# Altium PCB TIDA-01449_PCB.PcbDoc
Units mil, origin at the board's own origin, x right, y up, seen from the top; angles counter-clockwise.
Board outline 718.74 x 413.39 mil, 2 copper layers (Top Layer, Bottom Layer), stack 62 mil thick; 17 components, 10 nets, 40 pads, 19 vias.
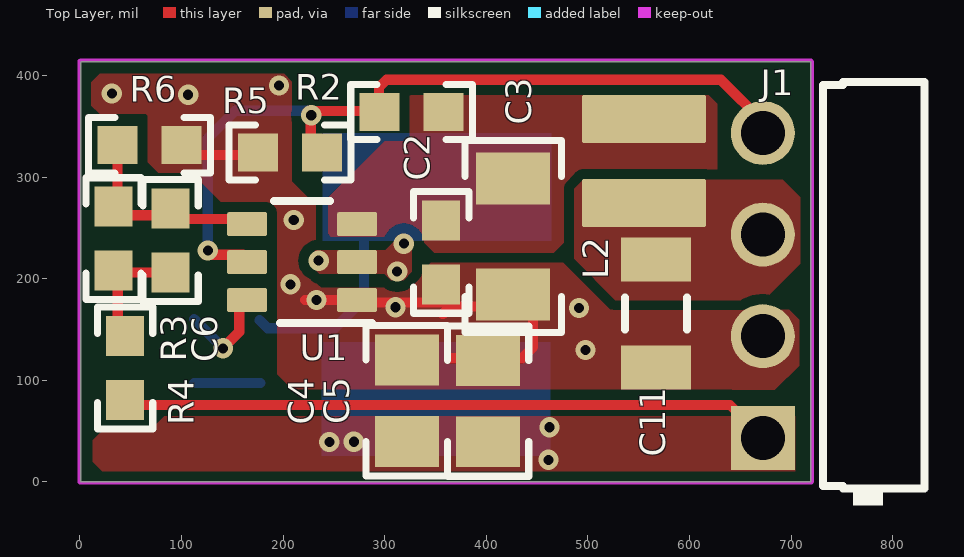
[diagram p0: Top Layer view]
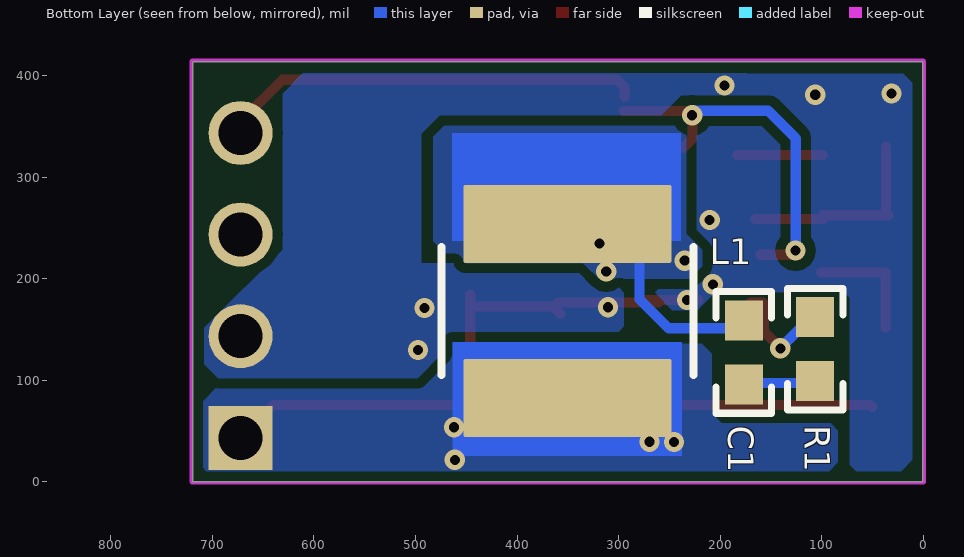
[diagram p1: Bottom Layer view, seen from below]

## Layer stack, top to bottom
Top Solder: solder mask 0.4, Solder Resist, Dk 3.5
Top Layer: signal copper 1.4
Dielectric1: core 59.2, FR-4, Dk 4.8
Bottom Layer: signal copper 1.4
Bottom Solder: solder mask 0.4, Solder Resist, Dk 3.5

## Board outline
0.56,0.27 0.56,413.66 719.3,413.66 719.3,0.27

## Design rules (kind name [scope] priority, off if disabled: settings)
AcuteAngle [All] p1: minimum=4.50000000000000E+0001 checktracksonly=FALSE
AssemblyTestPointUsage [All] p1: valid=2
BoardOutlineClearance BoardOutlineClearance_MountingHoles [OnCopper and InComponentClass('Mounting Holes')] p1: gap=40 ignorepadtopadclearanceinfootprint=FALSE
BoardOutlineClearance BoardOutlineClearance_Poly [OnCopper and IsPoly] p2: gap=10 ignorepadtopadclearanceinfootprint=FALSE
BoardOutlineClearance [OnCopper and Not InComponentClass('Logo') and not InComponentClass('FiducialMark') and not InRegion(1000,500,4000,800) and not InPoly] p3: gap=10 ignorepadtopadclearanceinfootprint=FALSE
Clearance Clearance_Keepouts [((IsTrack Or IsArc) And Not InPoly) And IsFree and IsKeepOut vs ((IsTrack Or IsArc) And Not InPoly) And IsFree and IsKeepOut] p1: gap=0 ignorepadtopadclearanceinfootprint=FALSE
Clearance Clearance_Poly [InPolygon] p2: gap=10 ignorepadtopadclearanceinfootprint=FALSE except(0: Arc-Hole Track-Hole SMDPad-Hole THPad-Hole Via-Hole Fill-Hole Poly-Hole Region-Hole Text-Hole)
Clearance [All] p3: gap=7.87 ignorepadtopadclearanceinfootprint=FALSE except(0: Arc-Hole Track-Hole SMDPad-Hole THPad-Hole Via-Hole Fill-Hole Poly-Hole Region-Hole Text-Hole)
ComponentClearance ComponentClearance_MountingHoles_FiducialMarks [InComponentClass('Mounting Holes') vs InComponentClass('FiducialMark')] p1: gap=50 collisioncheckmode=3 verticalgap=10 showdistances=FALSE
ComponentClearance ComponentClearance_Shunt [InComponentClass('Header') vs InComponentClass('Shunt')] p2: gap=0 collisioncheckmode=3 verticalgap=0 showdistances=FALSE
ComponentClearance ComponentClearance_Logo [InComponentClass('Logo')] p3: gap=50 collisioncheckmode=3 verticalgap=10 showdistances=FALSE
ComponentClearance ComponentClearance_ScrewToNut [(HasFootprint('NY PMS 440 0025 PH')) vs (HasFootprint('Keystone_1902C'))] p4: gap=5 collisioncheckmode=3 verticalgap=10 showdistances=FALSE
ComponentClearance ComponentClearance_MountingHoles [InComponentClass('Mounting Holes')] p5: gap=250 collisioncheckmode=3 verticalgap=100000 showdistances=FALSE
ComponentClearance ComponentClearance_SmallPassives [HasFootprint('0201*') or HasFootprint('0402*') or HasFootprint('0508') or HasFootprint('0603*') or HasFootprint('0612') or HasFootprint('0805*') or HasFootprint('0815*') or HasFootprint('0830*') or HasFootprint('1206*') or HasFootprint('1210*') or HasFootprint('1808*') or HasFootprint('1812*') or HasFootprint('1825*') or HasFootprint('2010*') or HasFootprint('2220*') or HasFootprint('2225*') or HasFootprint('2512*') or HasFootprint('2728*') or HasFootprint('3518*') vs HasFootprint('0201*') or HasFootprint('0402*') or HasFootprint('0508') or HasFootprint('0603*') or HasFootprint('0612') or HasFootprint('0805*') or HasFootprint('0815*') or HasFootprint('0830*') or HasFootprint('1206*') or HasFootprint('1210*') or HasFootprint('1808*') or HasFootprint('1812*') or HasFootprint('1825*') or HasFootprint('2010*') or HasFootprint('2220*') or HasFootprint('2225*') or HasFootprint('2512*') or HasFootprint('2728*') or HasFootprint('3518*')] p6: gap=14.96 collisioncheckmode=3 verticalgap=10 showdistances=FALSE
ComponentClearance ComponentClearance_THtoSMT [IsThruComponent vs IsSMTComponent] p7: gap=40 collisioncheckmode=3 verticalgap=30 showdistances=FALSE
ComponentClearance ComponentClearance_THtoSMT_1 [(ObjectKind = 'Component') And (Name = 'L2') vs (ObjectKind = 'Component') And (Name = 'C11')] p8: gap=18 collisioncheckmode=3 verticalgap=30 showdistances=FALSE
ComponentClearance ComponentClearance_THtoTH [IsThruComponent vs IsThruComponent] p9: gap=30 collisioncheckmode=3 verticalgap=30 showdistances=FALSE
ComponentClearance [All] p10: gap=30 collisioncheckmode=3 verticalgap=10 showdistances=FALSE
DiffPairsRouting [All] p1: maxlimit=100 minlimit=10 mostfreqgap=10 toplayer_minwidth=15 toplayer_maxwidth=15 toplayer_prefwidth=15 bottomlayer_minwidth=15 bottomlayer_maxwidth=15 bottomlayer_prefwidth=15 maxuncoupledlength=1000
FabricationTestPointUsage TestPointUsage [All] p1: valid=2 allowmultiple=FALSE
FabricationTestpoint Testpoint [All] p1: side=3 testpointundercomponent=TRUE minsize=40 maxsize=100 preferedsize=60 minholesize=0 maxholesize=40 preferedholesize=32 testpointgrid=1 allowsidetop=TRUE allowsidebottom=TRUE usegrid=TRUE gridtolerance=0.01
FanoutControl Fanout_LCC [IsLCC] p1: bgadir=Out bgaviamode=Centered fanoutstyle=Auto fanoutdirection=Alternating viagrid=1 // Fanout_LCC (Default Rule)
FanoutControl Fanout_BGA [IsBGA] p2: bgadir=Out bgaviamode=Centered fanoutstyle=Auto fanoutdirection=Alternating viagrid=1 // Fanout_BGA (Default Rule)
FanoutControl Fanout_Default [All] p4: bgadir=Out bgaviamode=Centered fanoutstyle=Auto fanoutdirection=Alternating viagrid=1 // Fanout_Default (Default Rule)
FanoutControl Fanout_Small [(CompPinCount < 5)] p5: bgadir=Out bgaviamode=Centered fanoutstyle=Auto fanoutdirection=OutThenIn viagrid=1 // Fanout_Small (Default Rule)
HoleSize [All] p1: absolutevalues=TRUE maxlimit=251 minlimit=7.87 maxpercent=80.000 minpercent=20.000
MinimumAnnularRing MinimumAnnularRing_ThermalPadVias [IsVia and InAnyComponent] p1: minimumring=5.91
MinimumAnnularRing [All] p2: minimumring=8
MinimumSolderMaskSliver MinimumSolderMaskSliver_Logo [InComponentClass('Logo') vs InComponentClass('Logo')] p1: minsoldermaskwidth=0.7
MinimumSolderMaskSliver [All] p2: minsoldermaskwidth=3.94
PlaneConnect [All] p1: planeconnectstyle=Relief reliefexpansion=10 reliefentries=4 reliefconductorwidth=10 reliefairgap=10
PolygonConnect [All] p1: connectstyle=Direct reliefconductorwidth=10 reliefentries=4 polygonreliefangle="90 Angle" airgapwidth=10
RoutingVias ThermalPadVias [IsVia and InAnyComponent] p1: holewidth=7.87 width=19.68 viastyle="Through Hole" minholewidth=7.87 minwidth=19.68 maxholewidth=12.99 maxwidth=23.62
RoutingVias [All] p2: holewidth=16 width=34 viastyle="Through Hole" minholewidth=7.87 minwidth=26 maxholewidth=40 maxwidth=65
SilkToBoardRegionClearance [Not ((IsComment or IsDesignator) And (Hide <> 'False')) and not InRegion(1000,500,4000,800)] p1:
SilkToSilkClearance SilkToSilkClearance_Pb-FreeLogo [(HasFootprint('Pb-Free_Overlay_Medium') OR HasFootprint('Pb-Free_Overlay_Small')) vs (HasFootprint('Pb-Free_Overlay_Medium') OR HasFootprint('Pb-Free_Overlay_Small'))] p1: silktosilkclearance=0
SilkToSilkClearance [All] p2: silktosilkclearance=4
SilkToSolderMaskClearance SilkToComponentPadClearance [(IsPad or IsFill or IsRegion) and InAnycomponent] p1: minsilkscreentomaskgap=5 clearancetoexposedcopper=TRUE
SilkToSolderMaskClearance "Silk to Solder Mask Opening" [All] p2: minsilkscreentomaskgap=4 clearancetoexposedcopper=FALSE
SolderMaskExpansion [All] p1: expansion=1.97
Width [All] p1: maxlimit=100 minlimit=6 preferedwidth=10 checkconnectedcopper=TRUE
15 further rules are at their usual default settings.

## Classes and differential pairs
component class Header: J1

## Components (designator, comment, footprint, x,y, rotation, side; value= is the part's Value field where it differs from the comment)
C1 "GRM188R70J104KA01D" 0603 176.85,127.55 r90 bottom value=0.1uF
C2 "885012206071" 0603 355.54,225.9 r270 top value=0.1uF
C3 "GMK316AB7106KL" 1206 426.44,241.54 r270 top value=10uF
C4 "GRM21BZ71A226ME15L" 0805_HV 321.67,79.86 r90 top value=22uF
C5 "GRM21BZ71A226ME15L" 0805_HV 401.78,79.54 r90 top value=22uF
C6 "GRM1885C1H220JA01D" 0603 89.22,237.47 r90 top value=22pF
C11 "C3216X5R1E476M160AC" 1206_190L 566.93,165.76 r270 top value=47uF
J1 "61300411021" Wurth_61300411021 672.11,193.4 r90 top
L1 "ABG06A45M3R3" ABG06A45 350.42,168.21 r270 bottom value=3.3uH
L2 "ABG03A15M4R7" ABG03A15 555.15,315.82 r90 top value=4.7uH
R1 "CRCW06030000Z0EA" 0603 106.52,130.53 r270 bottom value=0
R2 "CRCW060380K6FKEA" 0603 326.56,364.03 r0 top value=80.6k
R3 "CRCW060333K2FKEA" 0603 33,239.37 r270 top value=33.2k
R4 "CRCW060351R0JNEA" 0603 44.37,112.03 r270 top value=51
R5 "CRCW060349K9FKEA" 0603 206.65,324.14 r0 top value=49.9k
R6 "RCG060310K0FKEA" 0603 68.49,331.36 r180 top value=10.0k
U1 "TPS561201DDCR" DDC0006A_N 218.61,216.39 r180 top

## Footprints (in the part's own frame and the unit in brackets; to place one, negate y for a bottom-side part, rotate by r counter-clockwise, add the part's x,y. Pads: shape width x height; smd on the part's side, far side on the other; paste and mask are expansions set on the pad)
0603 [mm] "0603 from SM-752 data"
  rect 1x0.95 smd: 1(-0.8,0) 2(0.8,0)
  silkscreen extent -1.52,-0.69 1.52,0.69, body extent -0.87,-0.47 0.87,0.47, height 1
0805_HV [mil] "0805 with 30mil clearance between pads"
  rect 50x63 smd: 1(-40,0) 2(40,0)
  silkscreen extent -74,-40 74,40, body extent -43,-29 43,29, height 57
1206 [mm] "1206 from SM-752 data"
  rect 1.3x1.85 smd: 1(-1.45,0) 2(1.45,0)
  silkscreen extent -2.4,-1.21 2.4,1.21, body extent -1.7,-0.9 1.7,0.9, height 1.35
1206_190L [mm] "1206_190"
  rect 1.1x1.75 smd: 1(-1.35,0) 2(1.35,0)
  silkscreen extent -0.4,-0.77 0.4,0.77, body extent -1.75,-0.95 1.75,0.95, height 1.9
ABG03A15 [mm] "SMD, 2-Leads, Body 3x3mm"
  rrect8% 1.2x3.1 smd: 1(-1.05,0) 2(1.05,0)
  body extent -1.6,-1.6 1.6,1.6, height 1.5
ABG06A45 [mm] "SMD, 2-Leads, Body 6x6mm"
  rrect5% 1.95x5.2 smd: 1(-2.175,0) 2(2.175,0)
  silkscreen extent -1.6,-3.15 1.6,3.15, body extent -3.15,-3.15 3.15,3.15, height 4.5
DDC0006A_N [mm]
  rrect17% 1x0.6 smd: 1(-1.375,0.95) 2(-1.375,0) 3(-1.375,-0.95) 4(1.375,-0.95) 5(1.375,0) 6(1.375,0.95)
  silkscreen extent -1.75,-1.52 0.7,1.53, body extent -1.43,-1.48 1.43,1.49, height 0.92
Wurth_61300411021 [mm] "Header, 2.54 mm, 4x1, R/A, TH"
  rect 1.6x1.6 hole 1.1: 1(-3.81,0)
  round 1.6 hole 1.1: 2(-1.27,0) 3(1.27,0) 4(3.81,0)
  silkscreen extent -5.5,-4.04 5.08,-1.5, body extent -5.08,-10.04 5.08,0.32, height 2.55

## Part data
C1: "CAP, CERM, 0.1 µF, 6.3 V, +/- 10%, X7R, 0603", Cap_Case=0603, Manufacturer=MuRata, Supplier Part Number 1=GRM188R70J104KA01D-ND, TempCo=X7R, Tolerance_%=10, Value1=Unknown, Value2=6.3V, ValueDisplayed=0.1µF
C2: "CAP, CERM, 0.1 µF, 25 V, +/- 10%, X7R, 0603", Cap_Case=0603, Manufacturer="Wurth Elektronik", Supplier Part Number 1=710-885012206071, TempCo=X7R, Tolerance_%=10, Value1=Unknown, Value2=25V, ValueDisplayed=0.1µF
C3: "CAP, CERM, 10 µF, 35 V, +/- 10%, X7R, 1206", Cap_Case=1206, Manufacturer="Taiyo Yuden", Supplier Part Number 1=587-3007-1-ND, TempCo=X7R, Tolerance_%=10, Value1=Unknown, Value2=35V, ValueDisplayed=10µF
C4 C5: "CAP, CERM, 22 µF, 10 V, +/- 20%, X7R, 0805", Cap_Case=0805, Manufacturer=MuRata, Supplier Part Number 1=81-GRM21BZ71A226ME5L, TempCo=X7R, Tolerance_%=20, Value1=Unknown, Value2=10V, ValueDisplayed=22µF
C6: "CAP, CERM, 22 pF, 50 V, +/- 5%, C0G/NP0, 0603", Cap_Case=0603, Manufacturer=MuRata, Supplier Part Number 1=490-1411-1-ND, TempCo=C0G/NP0, Tolerance_%=5, Value1=Unknown, Value2=50V, ValueDisplayed=22pF
C11: "CAP, CERM, 47 µF, 25 V,+/- 20%, X5R, 1206", Cap_Case=1206, Manufacturer=TDK, Supplier Part Number 1=445-8047-1-ND, TempCo=X5R, Tolerance_%=20, Value2=25V, ValueDisplayed=47µF
J1: "Header, 2.54 mm, 4x1, Gold, R/A, TH", Color=Black, Manufacturer="Wurth Elektronik", Supplier Part Number 1=732-5337-ND
L1: "Inductor, 3.3 µH, 3.91 A, 0.026 ohm, SMD", Manufacturer=Coilank, Value1="0.026 ohm", Value2=3.91A, ValueDisplayed=3.3µH
L2: "Inductor, 4.7 µH, 1.12 A, 0.12 ohm, SMD", Manufacturer=Coilank, Value1="0.12 ohm", Value2=1.12A, ValueDisplayed=4.7µH
R1: "RES, 0, 5%, 0.1 W, 0603", Manufacturer=Vishay-Dale, Power_W=0.1, Supplier Part Number 1=541-0.0GCT-ND, TempCo="200 ppm/C", Tolerance_%=5, Value1=5%, Value2=0.1W, Value_Code=0000, ValueDisplayed=0
R2: "RES, 80.6 k, 1%, 0.1 W, 0603", Manufacturer=Vishay-Dale, Power_W=0.1, Supplier Part Number 1=541-80.6KHCT-ND, TempCo="100 ppm/C", Tolerance_%=1, Value1=1%, Value2=0.1W, Value_Code=80k6, ValueDisplayed=80.6k
R3: "RES, 33.2 k, 1%, 0.1 W, 0603", Manufacturer=Vishay-Dale, Power_W=0.1, Supplier Part Number 1=541-33.2KHCT-ND, TempCo="100 ppm/C", Tolerance_%=1, Value1=1%, Value2=0.1W, Value_Code=33k2, ValueDisplayed=33.2k
R4: "RES, 51, 5%, 0.1 W, 0603", Manufacturer=Vishay-Dale, Power_W=0.1, Supplier Part Number 1=541-51GCT-ND, TempCo="200 ppm/C", Tolerance_%=5, Value1=5%, Value2=0.1W, Value_Code=51R0, ValueDisplayed=51
R5: "RES, 49.9 k, 1%, 0.1 W, 0603", Manufacturer=Vishay-Dale, Power_W=0.1, Supplier Part Number 1=541-49.9KHCT-ND, TempCo="100 ppm/C", Tolerance_%=1, Value1=1%, Value2=0.1W, Value_Code=49k9, ValueDisplayed=49.9k
R6: "RES, 10.0 k, 1%, 0.1 W, 0603", Manufacturer="Vishay Draloric", Power_W=0.1, Supplier Part Number 1=541-1784-1-ND, TempCo="100 ppm/C", Tolerance_%=1, Value1=1%, Value2=0.1W, Value_Code=10k0, ValueDisplayed=10.0k
U1: "4.5-V to 17-V Input, 2-A Synchronous Step-Down Voltage Regulator, DDC0006A (SOT-23-T-6)", Alternate Manufacturer="Texas Instruments", Alternate PartNumber=TPS561201DDCT

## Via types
v1: diameter 20, hole 10, Top Layer to Bottom Layer, 19 vias

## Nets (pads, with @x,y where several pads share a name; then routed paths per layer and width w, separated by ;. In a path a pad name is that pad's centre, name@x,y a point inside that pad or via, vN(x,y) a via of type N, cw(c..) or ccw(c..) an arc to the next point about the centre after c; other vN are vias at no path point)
EN: J1.4 R2.1 R5.2 U1.5 | length 775.8
  Top Layer w10: v1@123.3,223.5 U1.5@160.32,223.5 ; R5.2@236.52,328.7 227.17,338.05 227.17,361.01 231.26,365.09 R2.1@295.19,365.09 ; R2.1@294.34,378.82 294.34,388.46 301.72,395.84 630.83,395.84 J1.4@673.35,353.33
  Bottom Layer w10: v1@125.7,226.43 125.7,338.09 152.9,365.28 v1@226.35,365.28
  other v1: 125.89,227.77 227.73,360.79
GND: C2.2 C3.2 C4.2 C5.2 C11.2 J1.2 R5.1 R6.1 U1.1 | length 461.6
  Top Layer w10: R6.1@99.08,321.63 R5.1@183.63,321.63 ; 221.59,178.99 U1.1 ; U1.1@261.05,176.51 C2.2@359.65,176.51 ; 357.12,165.13 364.72,172.73 C3.2@443.53,172.73 ; 364.3,121.73 435.1,121.73 446.06,132.69 C3.2@446.06,184.11
  other v1: 497.54,129.72 491.18,171.2 310.53,171.87 232.8,179.09 207.29,194.39 210.49,257.74 106.48,380.95 31.38,382.26 195.85,390.1
NetC1_1: C1.1 R1.2 | length 65.5
  Bottom Layer w10: R1.2@112.34,97.18 C1.1@177.87,97.18
NetC1_2: C1.2 L1.1 U1.2 | length 196.4
  Bottom Layer w10: C1.2 184.69,151.2 250.24,151.2 250.6,151.56 251.37,151.56 279.51,179.7 279.51,255.52 L1.1@282.43,255.52
  other v1: 312.21,207.03 234.91,217.74 318.83,234.47
NetC2_1: C2.1 C3.1 L2.2 R2.2 U1.3
NetC6_1: C6.1 R3.2 R4.1 | length 118.1
  Top Layer w10: R4.1@37.26,151.65 37.26,206.03 C6.1@101,206.03
NetC6_2: C6.2 R3.1 R6.2 U1.4 | length 202.1
  Top Layer w10: R3.1@34.32,262.38 C6.2@99.22,262.38 ; R6.2@36.83,329.93 36.83,266.29 R3.1@41.04,262.08 ; C6.2@98.26,258.62 U1.4@165.84,258.62
NetR1_1: R1.1 U1.6 | length 105.6
  Top Layer w10: v1@143.88,130.58 143.88,134.8 156.79,147.72 156.79,175.07 158.24,176.51 U1.6@170.19,176.51
  Bottom Layer w10: R1.1@112.34,160.17 v1@141.89,130.62
  other v1: 140.81,131.38
VIN: C11.1 J1.3 L2.1
VOUT: C4.1 C5.1 J1.1 L1.2 R4.2 | length 635.9
  Top Layer w10: R4.2@50.46,73.61 52.52,75.66 639.85,75.66 J1.1
  other v1: 461.18,21.67 245.51,39.29 269.58,39.55 462.1,53.79

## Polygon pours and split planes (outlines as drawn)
NetC2_1 on Top Layer "Vin" (solid, remove dead copper, pour order 45): 244.35,279.91 324.8,360.36 324.8,379.85 332.79,387.84 423.2,387.84 427.76,383.29 615.93,383.29 627.21,372.02 627.21,281.32 553.05,207.16 509.14,207.16 490.74,225.56 349.03,225.56 333.15,241.44 246.99,241.44 244.35,244.08
GND on Top Layer "GND" (solid, remove dead copper, pour order 44): 521.84,169.24 697.94,169.24 707.75,159.44 707.75,114.38 683.92,90.55 209.56,90.55 194.38,105.74 194.38,204.73 196.97,207.31 220.92,207.31 237.36,190.88 259.56,190.88 320.46,190.88 345.08,215.49 475.59,215.49
VOUT on Top Layer "Vout_kelvin" (solid, remove dead copper, pour order 43): 703.8,64.5 703.8,9.49 87.21,9.49 87.21,64.5
GND on Top Layer "GND2" (solid, remove dead copper, pour order 42): 236.21,194.11 231.94,198.28 231.94,272.33 208.52,295.75 208.52,349.13 208.52,395.58 202.58,401.52 19.6,401.52 11.26,393.17 11.26,370.14 19.27,362.13 64.97,362.13 66.67,360.43 66.67,314.73 77.29,304.12 110.16,304.12 120.94,293.34 138.59,275.69 181.29,275.69 194.32,262.65 194.32,184.35 200.88,177.79 234.17,177.79 236.21,179.84
NetC1_2 on Top Layer "SW" (solid, remove dead copper, pour order 41): 251.84,204.75 299.69,204.75 305.9,198.54 318.6,198.54 326.75,206.69 326.75,239.08 323.6,242.23 314.57,242.23 300.48,228.15 288.11,228.15 232.12,228.15 227.27,223.3 227.27,213.01 235.53,204.75
VIN on Top Layer "TOP_LAYER_VIN_P040" (solid, remove dead copper, pour order 40): 710.66,278.73 691.85,297.54 495.49,297.54 486.29,288.34 486.29,219.42 526.77,178.94 673.11,178.94 710.66,216.49
VOUT on Top Layer "TOP_LAYER_VOUT_P066" (solid, pour order 66): 103.65,64.43 82.76,64.43 67.6,49.27 21.1,49.27 12.78,40.94 12.78,19.81 22.36,10.22 112.8,10.22 123.36,20.79 123.36,58.14 117.22,64.29
GND on Bottom Layer "GND" (solid, pour order 50): 30.59,401.61 219.87,401.61 228.91,392.57 228.91,203.29 242.59,189.61 261.19,189.61 264.36,186.44 264.36,180.12 253.22,168.99 222.53,168.99 204.88,186.64 77.75,186.64 72.33,181.22 72.33,16.93 65.95,10.55 22.08,10.55 10.92,21.72 10.92,392.83 19.69,401.61
VOUT on Bottom Layer "Vout" (solid, remove dead copper, pour order 49): 219.92,137.45 464.4,137.44 476.16,125.69 476.17,22.09 464.42,10.35 93.08,10.35 84.23,19.2 84.23,50.6 91.22,57.59 198.58,57.59 208.47,67.48 208.47,126
NetC1_2 on Bottom Layer "SW" (solid, remove dead copper, pour order 48): 263.59,199.74 230.14,199.74 217.59,212.28 217.59,228.37 233.36,244.13 233.36,340.95 242.68,350.28 471.71,350.28 482.33,339.66 482.33,236.87 445.39,199.93 316.66,199.93
VOUT on Bottom Layer "Vout2" (solid, remove dead copper, pour order 47): 461.81,126.24 495.7,92.35 696.33,92.35 709.78,78.89 709.78,14.53 705.69,10.44 425.33,10.44 399.67,36.1 399.67,90.23 435.45,126
GND on Bottom Layer "GND2" (solid, pour order 46): 299.28,190.84 324.55,190.84 348.69,214.98 500.79,214.98 524.93,190.84 668.41,190.84 707.76,151.5 707.76,115.73 694.03,102 497.89,102 452.01,147.89 299.89,147.89 294.82,152.96 294.82,186.38
GND on Bottom Layer "BOTTOM_LAYER_GND_P062" (solid, remove dead copper, pour order 62): 533.19,152.94 652.29,152.94 672.08,172.73 672.08,187.21 630.74,228.55 630.74,382.03 610.82,401.95 172.89,401.95 166.57,395.64 166.57,384.86 170.94,380.49 238.29,380.49 258.07,360.71 475.93,360.71 494.23,342.42 494.23,191.9

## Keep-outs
Keep-Out Layer:
  lines w3: -0.94,0.27 ccw(c0.56,0.27) 0.56,-1.23 ; -0.94,0.27 ccw(c0.56,0.27) 0.56,-1.23 ; -0.94,0.27 -0.94,413.66 ; -0.94,413.66 cw(c0.56,413.66) 0.56,415.16 ; -0.94,413.66 cw(c0.56,413.66) 0.56,415.16 ; 0.56,-1.23 719.3,-1.23 ; 0.56,415.16 719.3,415.16 ; 719.3,-1.23 ccw(c719.3,0.27) 720.8,0.27 ; 719.3,-1.23 ccw(c719.3,0.27) 720.8,0.27 ; 719.3,415.16 cw(c719.3,413.66) 720.8,413.66 ; 719.3,415.16 cw(c719.3,413.66) 720.8,413.66 ; 720.8,0.27 720.8,413.66
  text ".Layer_Name" at 577,-858.49 h60

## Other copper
Top Layer:
  text ".Layer_Name" at 577,-858.49 h60
Bottom Layer:
  rectangle net NetC1_2: 238.71,237.28 464.17,343.41
  rectangle net VOUT: 237.84,25.63 463.31,137.6
  text ".Layer_Name" at 577,-858.49 h60

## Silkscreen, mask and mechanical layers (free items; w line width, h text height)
Top Overlay:
  text ".Layer_Name" at 577,-858.49 h60
Bottom Overlay:
  text ".Layer_Name" at 577,-858.49 h60
Top Paste:
  text ".Layer_Name" at 577,-858.49 h60
Bottom Paste:
  rectangle: 238.71,227.07 464.17,343.41
  rectangle: 237.84,25.63 463.31,137.6
  text ".Layer_Name" at 577,-858.49 h60
Top Solder:
  text ".Layer_Name" at 577,-858.49 h60
  text ".Layer_Name" at 577,-858.49 h60
Bottom Solder:
  rectangle: 238.71,225.84 464.17,343.41
  rectangle: 237.84,25.63 463.31,137.6
  text ".Layer_Name" at 577,-858.49 h60
Drill Guide:
  text ".Layer_Name" at 577,-858.49 h60
M1 Board Outline:
  the board outline again, w10
  text ".Layer_Name" at 577,-858.49 h60
M2 Board Dimensions:
  rectangle: 0,-275 125,-150
  rectangle: 125,-400 500,-275
  lines w7: 0,-275 1000,-275 ; 125,-400 125,-150 ; 250,-400 250,-150 ; 500,-400 500,-150 ; 750,-400 750,-150 ; 0,-400 1000,-400 1000,-150 0,-150 0,-400
  text ".Layer_Name" at 577,-858.49 h60
M3 3D STEP Top:
  text ".Layer_Name" at 577,-858.49 h60
M4 3D STEP Bottom:
  text ".Layer_Name" at 577,-858.49 h60
M5 Assembly Top:
  lines w10: -292,-930.17 6308,-930.17 ; -292,-726.83 6310,-726.83 ; -292,-523.5 -292,-1133.5 3713,-1133.5 6310,-1133.5 6310,-523.5 -291.5,-523.5 -291.5,-1133.5 1284,-1133.5 ; 2173,-1133.5 2173,-523.5 ; 3440,-726.83 3440,-523.5 ; 4280,-726.83 4280,-523.5 ; 4902,-1140 4902,-937.17
  text "COMPONENTS MARKED 'DNP' SHOULD NOT BE POPULATED." at 1153.5,-318.5 h60
  text "ASSEMBLY VARIANT:" at 1153,-434 h60
  text ".VariantName" at 2189,-434 h60
  text "PCB VIEWED FROM TOP SIDE" at -228.5,-655.67 h60
  text "BOARD #:" at 2248,-655.67 h60
  text ".PRJ_Number" at 2793.5,-655.67 h60
  text "REV:" at 3638,-655.67 h60
  text ".PCB_Rev" at 3929.5,-655.67 h60
  text "SVN REV:" at 4476,-655.67 h60
  text ".VersionControl_RevNumber" at 4982,-655.67 h60
  text "TID #:" at 2248,-859 h60
  text ".TID" at 2793.5,-859 h60
  text "PLOT NAME =" at -228.5,-1064.34 h60
  text ".plot_File_Name" at 577,-1064.34 h60
  text "GENERATED    :" at 2250,-1064.34 h60
  text ".Print_Date" at 3119.5,-1064.34 h60
  text ".Print_Time" at 3848.5,-1064.34 h60
  text "TEXAS INSTRUMENTS" at 5113,-1064.34 h60
M6 Assembly Bottom:
  lines w10: -292.5,-727.33 6309.5,-727.33 ; -290.5,-930.67 6309.5,-930.67 ; 1115.5,-1140.5 1115.5,-937.67 ; 1737.5,-727.33 1737.5,-524 ; 2577.5,-727.33 2577.5,-524 ; 3844.5,-1134 3844.5,-524 ; 4733.5,-1134 6309,-1134 6309,-524 -292.5,-524 -292.5,-1134 2304.5,-1134 6309.5,-1134 6309.5,-524
  text "COMPONENTS MARKED 'DNP' SHOULD NOT BE POPULATED." at 6102,-318 h60
  text ".VariantName" at 5058,-434 h60
  text "ASSEMBLY VARIANT:" at 6097,-434 h60
  text ".VersionControl_RevNumber" at 1035.5,-656.17 h60
  text "SVN REV:" at 1541.5,-656.17 h60
  text ".PCB_Rev" at 2088,-656.17 h60
  text "REV:" at 2379.5,-656.17 h60
  text ".PRJ_Number" at 3224,-656.17 h60
  text "BOARD #:" at 3769.5,-656.17 h60
  text "PCB VIEWED FROM BOTTOM SIDE" at 6246,-656.17 h60
  text ".TID" at 3224,-859.5 h60
  text "TID #:" at 3769.5,-859.5 h60
  text "TEXAS INSTRUMENTS" at 904.5,-1064.84 h60
  text ".Print_Time" at 2169,-1064.84 h60
  text ".Print_Date" at 2898,-1064.84 h60
  text "GENERATED    :" at 3767.5,-1064.84 h60
  text ".plot_File_Name" at 5440.5,-1064.84 h60
  text "PLOT NAME =" at 6246,-1064.84 h60
M9 Title Sheet:
  drawing of 57 lines, arcs and shapes, not listed
  text "1" at 739.84,8036.5 h70
  text "2" at 3235.5,8036.5 h70
  text "3" at 5724.84,8036.5 h70
  text "4" at 8231.51,8036.5 h70
  text "5" at 10730.5,8036.5 h70
  text "6" at 13235.5,8036.5 h70
  text "A" at -416.5,6893.5 h70
  text "A" at 14383.5,6893.5 h70
  text "B" at -416.5,4513.5 h70
  text "B" at 14383.5,4513.5 h70
  text "C" at -416.5,2138.5 h70
  text "C" at 14383.5,2138.5 h70
  text "PROJECT TITLE:" at 11343.5,277.5 h45
  text ".PRJ_Title" at 11393.5,144.17 h70
  text "DESIGNED FOR:" at 11343.5,-23.5 h45
  text ".PRJ_Customer" at 11393.5,-163.5 h70
  text "D" at -416.5,-231.5 h70
  text "D" at 14383.5,-231.5 h70
  text "FILE NAME:" at 11343.5,-323.5 h45
  text ".PCB_File_Name_No_Path" at 11393.5,-443.5 h70
  text "Texas Instruments (TI) and/or its licensors do not warrant the accuracy or completeness of this specification" at 6374,-605.34 h45
  text "ENGINEER:" at 11343.5,-613.5 h45
  text "LAYOUT BY:" at 12848.5,-613.5 h45
  text "or any information contained therein. TI and/or its licensors do not warrant that this design will meet" at 6329.01,-718 h45
  text ".PRJ_Engineer" at 11393.5,-768.49 h70
  text ".PCB_Layout" at 12899,-768.49 h70
  text "the specifications, will be suitable for your application or fit for any particular purpose, or will operate in" at 6329.01,-830.67 h45
  text ".Layer_Name" at 577,-858.49 h60
  text "ALTIUM DESIGNER VERSION:" at 12848.5,-923.5 h45
  text "an implementation. TI and/or its licensors do not warrant that the design is production worthy. You should" at 6329.01,-943.33 h45
  text "completely validate and test your design implementation to confirm the system functionality for your application." at 6374,-1056 h45
  text ".print_Scale" at 11393.5,-1056.83 h70
  text ".Application_BuildNumber" at 12899,-1056.83 h70
  text "1" at 739.84,-1263.5 h70
  text "2" at 3235.5,-1263.5 h70
  text "3" at 5724.84,-1263.5 h70
  text "4" at 8231.51,-1263.5 h70
  text "5" at 10730.5,-1263.5 h70
  text "6" at 13235.5,-1263.5 h70
M10 Fab Notes:
  drawing of 173 lines, arcs and shapes, not listed
  text "DESIGN INFORMATION" at 12378.02,6201 h60
  text "MIN. TRACK WIDTH:" at 11733.46,6021 h60
  text "8" at 12829.7,6021 h60
  text "MIL" at 12984.46,6021 h60
  text "MIN. CLEARANCE:" at 11733.46,5889 h60
  text "0.2" at 12769.7,5889 h60
  text "mm" at 12984.46,5889 h60
  text "MIN. VIA PAD SIZE:" at 11733.46,5757 h60
  text "24" at 12799.71,5757 h60
  text "MIL" at 12984.46,5757 h60
  text "0.05mm (2MIL)" at 12428.46,5615.29 h60
  text "MINIMUM ANNULAR RING" at 11404.23,5611 h60
  text "EXTERNAL" at 13136.46,5611 h60
  text "PER" at 11604.23,5493 h60
  text "IPC-D-275 CLASS 2 LEVEL C" at 11824.23,5493 h60
  text "MIL, HOLES" at 13312.46,5380.71 h60
  text "+/-" at 12920,5380 h60
  text "+/-" at 13774,5380 h60
  text "REGISTRATION TOLERANCES:" at 11404.23,5375 h60
  text "METAL" at 12604,5375 h60
  text "5" at 13180.2,5375 h60
  text "3" at 14013.2,5375 h60
  text "MIL" at 14129.46,5375 h60
  text "+/-" at 13774,5262 h60
  text "HOLE SIZE TOLERANCE (UNLESS OTHERWISE SPECIFIED):" at 11404.23,5257 h60
  text "3" at 14013.2,5257 h60
  text "MIL" at 14129.46,5257 h60
  text "MATERIAL:" at 11329.46,5047.54 h60
  text "FR-4 High Tg" at 12315.9,4907.21 h60
  text "FR-408" at 11750.46,4898.64 h60
  text "OTHER" at 13238.46,4898.64 h60
  text "X" at 12161,4895 h60
  text "62 MIL (1.6mm) +/-10%" at 12070.56,4735.92 h60
  text "THICKNESS:" at 11404.23,4731.64 h60
  text "X" at 11942.4,4731.64 h60
  text "OTHER" at 13355.46,4731.64 h60
  text "TOLERANCE:" at 11404.23,4573.64 h60
  text "X" at 12243.53,4573.64 h60
  text "ANSI IPC-6012 TYPE 3 CLASS 2" at 12430.48,4573.64 h60
  text "OTHER +/-" at 12430.46,4417.64 h60
  text "BOW & TWIST:" at 11404.23,4260.64 h60
  text "X" at 12243.53,4260.64 h60
  text "ANSI IPC-6012 TYPE 3 CLASS 2" at 12430.48,4260.64 h60
  text "OTHER +/-" at 12430.46,4102.13 h60
  text "DRILLING:" at 11329.46,3963.64 h60
  text "REFERENCE:" at 11404.23,3846.64 h60
  text "X" at 12052.46,3846.64 h60
  text "AS SHOWN" at 12239.46,3846.64 h60
  text "X" at 12953.46,3846.64 h60
  text "NC_DRILL FILES" at 13090.46,3846.64 h60
  text "PTH COPPER THICKNESS:" at 11404.23,3688.64 h60
  text "X" at 12534.46,3688.64 h60
  text "20-30 um" at 12671.46,3688.64 h60
  text "OTHER" at 13388.46,3688.64 h60
  text "BOARD FINISH:" at 11329.46,3529.64 h60
  text "SILKSCREEN:" at 11484.68,3411.64 h60
  text "X" at 12433.46,3411.64 h60
  text "TOP" at 12559.46,3411.64 h60
  text "X" at 12943.46,3411.64 h60
  text "BOTTOM" at 13070.46,3411.64 h60
  text "SILKSCREEN COLOR:" at 11484.68,3244.64 h60
  text "X" at 12432.42,3244.64 h60
  text "WHITE" at 12559.46,3244.64 h60
  text "OTHER" at 13070.46,3244.64 h60
  text "X" at 12563.42,3085.44 h60
  text "GREEN" at 12690.46,3085.44 h60
  text "OTHER" at 13308.46,3085.44 h60
  text "SOLDER RESIST COLOR:" at 11484.68,3074.64 h60
  text "X" at 12563.42,2915.44 h60
  text "MATTE" at 12690.46,2915.44 h60
  text "SEMI-GLOSS" at 13308,2914.8 h60
  text "IMMERSION GOLD (ENIG)" at 12390.46,2726.92 h60
  text "ENEPIG" at 13728,2723.64 h60
  text "SURFACE FINISH:" at 11329.46,2722.64 h60
  text "X" at 12203.51,2722.64 h60
  text "IMM. TIN/SILVER OR EQUIV" at 11659,2565.64 h60
  text "OTHER" at 13090.46,2565.64 h60
  text "ARRAY/PANEL:" at 11329.46,2386.64 h60
  text "CUT AND TRIM PER M1 BOARD OUTLINE" at 12390.46,2382.35 h60
  text "N.C. ROUTE" at 12390.46,2230.64 h60
  text "X" at 13069.46,2230.64 h60
  text "V. SCORE" at 13256.46,2230.64 h60
  text "CERTIFICATION:" at 11329.46,2093.64 h60
  text "MATERIALS AND WORKMANSHIP FOR ALL PCBS" at 12054.46,2093.64 h60
  text "TO MEET OR EXCEED THE REQUIREMENTS OF:" at 12054.46,1995.64 h60
  text "X" at 11680.96,1859.13 h60
  text "ANSI IPC-A-600F CLASS ->" at 11819.96,1859.13 h60
  text "X" at 13459.02,1859.13 h60
  text "2" at 13577.96,1859.14 h60
  text "1" at 13262.96,1857.64 h60
  text "3" at 13931.96,1857.64 h60
  text "X" at 12495.02,1699.64 h60
  text "RoHS" at 12631.96,1699.64 h60
  text "OTHER" at 13276.36,1699.64 h60
  text "PER ORDER" at 13673.42,1699.64 h60
  text "ALL BOARDS MUST MEET OR EXCEED UL94-V0 REQUIREMENTS." at 11357,1534 h60
  text "PCB MUST BEAR THE UL94V-0 UL REGISTERED MATERIAL ID NUMBER" at 11357,1414 h60
  text "ADDITIONAL REQUIREMENTS:" at 11329.46,1240.64 h60
  text "MICROSECTION:" at 11404.23,1125.64 h60
  text "YES" at 12309.96,1125.64 h60
  text "REQUIRED" at 13171.46,969.49 h60
  text "BARE BOARD ELEC. TEST:" at 11404.23,966.64 h60
  text "NONE" at 12709.96,966.64 h60
  text "X" at 13044.46,966.64 h60
  text "PER ORDER" at 13763.46,966.64 h60
  text ".Layer_Name" at 577,-858.49 h60
M11 Gerber Information:
  lines w10: -292,-930.17 6308,-930.17 ; -292,-726.83 6310,-726.83 ; -292,-523.5 -292,-1133.5 3713,-1133.5 6310,-1133.5 6310,-523.5 -291.5,-523.5 -291.5,-1133.5 1284,-1133.5 ; 2173,-1133.5 2173,-523.5 ; 3440,-726.83 3440,-523.5 ; 4280,-726.83 4280,-523.5 ; 4902,-1140 4902,-937.17
  text "ALL ARTWORK VIEWED FROM TOP SIDE" at -228.5,-655.67 h60
  text "BOARD #:" at 2248,-655.67 h60
  text ".PRJ_Number" at 2793.5,-655.67 h60
  text "REV:" at 3638,-655.67 h60
  text ".PCB_Rev" at 3929.5,-655.67 h60
  text "SVN REV:" at 4476,-655.67 h60
  text ".VersionControl_RevNumber" at 4982,-655.67 h60
  text "LAYER NAME =" at -228.5,-858.49 h60
  text "TID #:" at 2248,-859 h60
  text ".TID" at 2793.5,-859 h60
  text "PLOT NAME =" at -228.5,-1064.34 h60
  text ".plot_File_Name" at 577,-1064.34 h60
  text "GENERATED    :" at 2250,-1064.34 h60
  text ".Print_Date" at 3119.5,-1064.34 h60
  text ".Print_Time" at 3848.5,-1064.34 h60
  text "TEXAS INSTRUMENTS" at 5113,-1064.34 h60
M12 Stackup:
  drawing of 191 lines, arcs and shapes, not listed
  text "Layer" at 9790.34,7830 h60
  text "Name" at 10200.26,7830 h60
  text "Material" at 11130,7830 h60
  text "Thickness" at 11989.77,7830 h60
  text "Constant" at 12639.6,7830 h60
  text "Board Layer Stack" at 13209.46,7830 h60
  text "1" at 9790.34,7710 h60
  text "Top Overlay" at 10200.26,7710 h60
  text "2" at 9790.34,7590 h60
  text "Top Solder" at 10200.26,7590 h60
  text "Solder Resist" at 11130,7590 h60
  text "0.40mil" at 11989.77,7590 h60
  text "3.5" at 12639.6,7590 h60
  text "3" at 9790.34,7470 h60
  text "Top Layer" at 10200.26,7470 h60
  text "Copper" at 11130,7470 h60
  text "1.40mil" at 11989.77,7470 h60
  text "4" at 9790.34,7350 h60
  text "Dielectric1" at 10200.26,7350 h60
  text "FR-4" at 11130,7350 h60
  text "59.20mil" at 11989.77,7350 h60
  text "4.8" at 12639.6,7350 h60
  text "5" at 9790.34,7230 h60
  text "Bottom Layer" at 10200.26,7230 h60
  text "Copper" at 11130,7230 h60
  text "1.40mil" at 11989.77,7230 h60
  text "6" at 9790.34,7110 h60
  text "Bottom Solder" at 10200.26,7110 h60
  text "Solder Resist" at 11130,7110 h60
  text "0.40mil" at 11989.77,7110 h60
  text "3.5" at 12639.6,7110 h60
  text "7" at 9790.34,6990 h60
  text "Bottom Overlay" at 10200.26,6990 h60
  text ".Layer_Name" at 577,-858.49 h60
M13 Component Bodies Top:
  text ".Layer_Name" at 577,-858.49 h60
M14 Component Bodies Bottom:
  text ".Layer_Name" at 577,-858.49 h60
M15 Courtyards Top:
  text ".Layer_Name" at 577,-858.49 h60
M16 Courtyards Bottom:
  text ".Layer_Name" at 577,-858.49 h60
Drill Drawing:
  lines w10: 5336.1,3169.56 5391.36,3169.56 5363.73,3114.3 5336.1,3169.56 ; 5336.1,3238.63 5391.36,3238.63 5391.36,3293.89 5336.1,3293.89 5336.1,3238.63
  lines w12: 5286,3076.99 8516.06,3076.99 ; 5286,3325.66 8516.06,3325.66 ; 5623.75,2952.66 5623.75,3450 ; 5955.56,2952.66 5955.56,3450 ; 6591.66,2952.66 6591.66,3450 ; 6850.66,2952.66 6850.66,3450 ; 7225.64,2952.66 7225.64,3450 ; 7949.86,2952.66 7949.86,3450 ; 5286,2952.66 8516.06,2952.66 8516.06,3450 5286,3450 5286,2952.66
  text "Symbol" at 5360.6,3362.97 h72
  text "Quantity" at 5661.05,3362.97 h72
  text "Finished Hole Size" at 5992.86,3362.97 h72
  text "Plated" at 6628.96,3362.97 h72
  text "Hole Type" at 6887.96,3362.97 h72
  text "Drill Layer Pair" at 7262.94,3362.97 h72
  text "Hole Tolerance" at 7987.16,3362.97 h72
  text "19" at 5661.05,3238.63 h60
  text "10.00mil (0.254mm)" at 5992.86,3238.63 h60
  text "PTH" at 6628.96,3238.63 h60
  text "Round" at 6887.96,3238.63 h60
  text "Top Layer - Bottom Layer" at 7262.94,3238.63 h60
  text "4" at 5661.05,3114.3 h60
  text "43.31mil (1.100mm)" at 5992.86,3114.3 h60
  text "PTH" at 6628.96,3114.3 h60
  text "Round" at 6887.96,3114.3 h60
  text "Top Layer - Bottom Layer" at 7262.94,3114.3 h60
  text "23 Total" at 5661.05,2989.96 h60
  text ".Layer_Name" at 577,-858.49 h60
M17 Embedded Cavity:
  text ".Layer_Name" at 577,-858.49 h60
M18 Embedded Assembly:
  text ".Layer_Name" at 577,-858.49 h60
M19 Embedded Keepout:
  text ".Layer_Name" at 577,-858.49 h60

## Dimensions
0,-400 to 1000,-400 on M2 Board Dimensions
0.56,0.27 to 719.3,0.27 on M2 Board Dimensions
0.56,0.27 to 0.56,413.66 on M2 Board Dimensions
